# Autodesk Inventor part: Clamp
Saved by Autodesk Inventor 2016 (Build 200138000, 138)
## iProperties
Created: 2015-11
Part Number: Clamp
Material: Generic
Document SubType Name: Modeling
Designer: John
Density: 1 g/cm^3
Appearance: Default
Author: John
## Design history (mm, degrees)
feature "SOLID1"
body "Solid1"
